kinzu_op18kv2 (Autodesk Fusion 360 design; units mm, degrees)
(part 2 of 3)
sketch "スケッチ73" plane through (0, 0, 0) normal (0, 0, 1) x axis (1, 0, 0)
  line L1 (-7.4, 45.9378) -> (-7.4, 47.6699)
  line L2 (7.4, 45.9378) -> (14.6149, 45.9378)
  line L3 (7.4, 47.6699) -> (7.4, 45.9378)
  line L4 (-7.4, 47.6699) -> (-15.2119, 47.6699)
  line L5 (-15.2119, 47.6699) -> (-7.4, 47.6699)
  line L6 (6.1, 41.5) -> (6.1, 45)
  line L7 (2.5, 42.5) -> (2.5, 41.5)
  line L8 (4.9, 42.5) -> (2.5, 42.5)
  line L9 (4.9, 45) -> (4.9, 42.5)
  line L10 (-2.5, 45) -> (-2.5, 46)
  line L11 (-4.9, 42.5) -> (-4.9, 45)
  line L12 (-2.5, 42.5) -> (-4.9, 42.5)
  line L13 (-2.5, 41.5) -> (-2.5, 42.5)
  line L14 (-6.1, 41.5) -> (-2.5, 41.5)
  line L15 (-6.1, 45) -> (-6.1, 41.5)
  line L16 (-50, 41.5) -> (50, 41.5)
  line L17 (-7.4, 41.5) -> (-7.4, 45)
  line L18 (-0.0015, 75) -> (-0.0015, 100)
  line L19 (50, -70) -> (-50, -70)
  line L20 (50, 70) -> (50, -70)
  line L21 (-50, 70) -> (50, 70)
  line L22 (-50, -70) -> (-50, 70)
  line L23 (50, 70) -> (-50, -70)
  line L24 (-50, 70) -> (50, -70)
  line L25 (-7.4, 70) -> (-7.4, 47.6699)
  line L26 (7.4, 41.5) -> (7.4, 45)
  line L27 (7.4, 70) -> (7.4, 47.6699)
  line L28 (2.5, 41.5) -> (6.1, 41.5)
  line L29 (7.4, 46) -> (2.5, 46)
  line L30 (6.1, 45) -> (7.4, 45)
  line L31 (2.5, 45) -> (4.9, 45)
  line L32 (2.5, 46) -> (2.5, 45)
  line L33 (-2.5, 46) -> (-7.4, 46)
  line L34 (-4.9, 45) -> (-2.5, 45)
  line L35 (-7.4, 45) -> (-6.1, 45)
  line L36 (8.6, 45.9378) -> (7.4, 45.9378)
  line L37 (8.6, 45) -> (8.6, 45.9378)
  line L38 (7.4, 45) -> (8.6, 45)
  line L39 (7.4, 45.9378) -> (7.4, 45)
  line L40 (-7.4, 45.9378) -> (-8.6, 45.9378)
  line L41 (-7.4, 45) -> (-7.4, 45.9378)
  line L42 (-8.6, 45) -> (-7.4, 45)
  line L43 (-8.6, 45.9378) -> (-8.6, 45)
  line L44 (-50, 47.6699) -> (-15.2119, 47.6699)
  line L45 (50, 47.6699) -> (15.2119, 47.6699)
  line L46 (-45, -5) -> (-45, 50)
  line L47 (45, -5) -> (45, 50)
  curve K1 (19.2629, 45.9378) -> (28.3953, -26.5255)
  curve K2 (15.2119, 47.6699) -> (19.2629, 45.9378)
  line L48 (7.4, 47.6699) -> (15.2119, 47.6699)
  line L49 (7.4, 45.9378) -> (7.4, 47.6699)
  line L50 (14.6149, 45.9378) -> (7.4, 45.9378)
  curve K3 (26.4543, -26.6056) -> (14.6149, 45.9378)
  curve K4 (-26.4543, -26.6056) -> (26.4543, -26.6056)
  curve K5 (-14.6149, 45.9378) -> (-26.4543, -26.6056)
  line L51 (-7.4, 45.9378) -> (-14.6149, 45.9378)
  line L52 (-7.4, 47.6699) -> (-7.4, 45.9378)
  line L53 (-15.2119, 47.6699) -> (-7.4, 47.6699)
  curve K6 (-19.2629, 45.9378) -> (-15.2119, 47.6699)
  curve K7 (-28.3953, -26.5255) -> (-19.2629, 45.9378)
  curve K8 (28.3953, -26.5255) -> (-28.3953, -26.5255)
  curve K9 (20.4801, -27.687) -> (-20.4801, -27.687)
  curve K10 (-24.4377, -27.1062) -> (-17.3148, 42.4442)
  curve K11 (17.3148, 42.4442) -> (24.4377, -27.1062)
  line L54 (14.7506, 70) -> (14.7506, 41.5)
  line L55 (-14.7512, 70) -> (-14.7512, 41.5)
  line L56 (-50, 4.113) -> (-21.6092, -24.2778)
  line L57 (-7, -23) -> (-20.387, -23)
  line L58 (50, 4.113) -> (21.6092, -24.2778)
  line L59 (45, -24) -> (20.887, -24)
  line L60 (48.6618, 5.9319) -> (8.6559, 45.9378)
  line L61 (-53.85, 0.7444) -> (-8.6565, 45.9378)
  line L62 (-10.164, 45) -> (-8.6, 45)
  line L63 (10.5, 45) -> (8.6, 45)
  line L64 (15.2119, 47.6699) -> (7.4, 47.6699)
  circle C1 centre (-24.4377, -27.1062) radius 4
  circle C2 centre (24.4377, -27.1062) radius 4
  circle C3 centre (-18.7512, 41.5) radius 4
  circle C4 centre (18.7506, 41.5) radius 4
  point P8 (-7.4, 47.6699)
  point P9 (-7.4, 47.6699)
  point P2 (-15.2119, 47.6699)
  point P10 (-15.2119, 47.6699)
  point P25 (-7.4, 41.5)
  point P32 (0, 0)
  point P1 (0, 0)
  point P3 (-7.4, 47.6699)
  point P33 (-7.4, 47.6699)
  point P34 (-7.4, 70)
  point P36 (7.4, 41.5)
  point P7 (7.4, 47.6699)
  point P37 (7.4, 47.6699)
  point P38 (7.4, 70)
  point P59 (-50, 47.6699)
  point P61 (50, 47.6699)
  point P83 (-24.4377, -27.1062)
  point P86 (-24.4377, -27.1062)
  point P84 (24.4377, -27.1062)
  point P87 (24.4377, -27.1062)
  point P88 (-18.7512, 41.5)
  point P89 (18.7506, 41.5)
  point P90 (14.7506, 41.5)
  point P91 (14.7506, 70)
  point P92 (-14.7512, 41.5)
  point P93 (-14.7512, 70)
  point P96 (-21.6092, -24.2778)
  point P99 (21.6092, -24.2778)
  point P100 (50, 4.113)
  point P101 (-50, 4.113)
  point P104 (8.6559, 45.9378)
  point P58 (-8.6, 45)
  point P106 (-8.6, 45)
  point P53 (8.6, 45)
  point P108 (8.6, 45)
  coincident P8 P9
  coincident P2 P10
  horizontal L16
  collinear L14 L16
  coincident L16 P25
  perpendicular L16 L17
  vertical L18
  horizontal L19
  perpendicular L19 L20
  parallel L19 L21
  parallel L20 L22
  coincident L23 P32
  coincident L24 P32
  coincident P1 P32
  coincident P3 P33
  coincident L21 P34
  perpendicular L21 L25
  coincident L16 P36
  perpendicular L16 L26
  coincident P7 P37
  coincident L21 P38
  perpendicular L21 L27
  coincident L22 P59
  perpendicular L22 L44
  coincident L20 P61
  perpendicular L20 L45
  perpendicular L44 L46
  perpendicular L16 L47
  coincident P83 P86
  coincident P84 P87
  coincident K10 P88
  coincident L16 P88
  coincident K11 P89
  coincident L16 P89
  coincident C4 P90
  coincident L16 P90
  coincident L21 P91
  tangent C4 L54
  coincident L16 P92
  coincident C3 P92
  coincident L21 P93
  tangent C3 L55
  horizontal L57
  tangent C1 L56
  coincident C1 P96
  horizontal L59
  tangent C2 L58
  coincident C2 P99
  coincident L20 P100
  coincident L22 P101
  tangent C4 L60
  tangent C3 L61
  coincident L2 P104
  coincident P58 P106
  perpendicular L43 L62
  coincident P53 P108
  perpendicular L37 L63
  dimension "d1064" = -8
  dimension "d1065" = -4
  dimension "d1069" diameter C1 = 8
  dimension "d1070" diameter C2 = 8
  dimension "d1071" diameter C3 = 8
  dimension "d1072" diameter C4 = 8
  dimension "d1073" angle L56 L57 = 135
  dimension "d1074" angle L58 L59 = 45
  dimension "d1157" angle L20 L60 = 45
  dimension "d1158" angle L22 L61 = 45
extrude "押し出し167" new body sketch "スケッチ73" profile of L1 L2 L3 L4 L5 L16 L19 L20 L22 L36 L37 L38 L39 L40 L41 L42 L43 L44 L45 L46 L47 K1 K2 L48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 along normal blind 2 bodies "feet"
combine "結合48"
sketch "スケッチ61" plane through (0, 0, 0) normal (0, 1, 0) x axis (1, 0, 0)
  line L1 (-50, 0) -> (50, 0)
  line L2 (0, -50) -> (0, 0)
  line L3 (-53.1, -8.7) -> (46.9, -8.7)
  curve K1 (-23.0212, -6.7064) -> (-3.1, -8.7)
  curve K2 (-26.0212, -6.7064) -> (-20.0212, -6.7064)
  curve K3 (-5.6533, -8.7) -> (-0.5467, -8.7)
  line L4 (-50, -6.7064) -> (-23.0212, -6.7064)
  line L5 (-40, -20) -> (-40, 5)
  line L6 (40, -20) -> (40, 5)
  line L7 (-3.1, -8.7) -> (0, -8.7)
  line L8 (-3.1, -10.2) -> (0, -10.2)
  curve K4 (-23.0212, -8.2064) -> (-3.1, -10.2)
  line L9 (-50, -8.2064) -> (-23.0212, -8.2064)
  line L10 (50, -8.2064) -> (23.0212, -8.2064)
  line L11 (50, -6.7064) -> (23.0212, -6.7064)
  curve K5 (23.0212, -6.7064) -> (3.1, -8.7)
  curve K6 (5.6533, -8.7) -> (0.5467, -8.7)
  curve K7 (26.0212, -6.7064) -> (20.0212, -6.7064)
  curve K8 (23.0212, -8.2064) -> (3.1, -10.2)
  line L12 (3.1, -8.7) -> (0, -8.7)
  line L13 (3.1, -10.2) -> (0, -10.2)
  line L14 (-3.1, -6.7) -> (0, -6.7)
  curve K9 (-23.0212, -4.7064) -> (-3.1, -6.7)
  line L15 (-50, -4.7064) -> (-23.0212, -4.7064)
  point P1 (0, 0)
  point P4 (0, 0)
  point P8 (-3.1, -8.7)
  point P20 (-23.0212, -6.7064)
  point P12 (-0.5467, -8.7)
  point P15 (-40, 5)
  point P17 (40, 5)
  point P16 (-40, -20)
  point P18 (40, -20)
  point P19 (0, -8.7)
  point P29 (3.1, -8.7)
  point P9 (-12, -7.8)
  point P30 (12, -7.8)
  point P10 (-20.0212, -6.7064)
  point P33 (20.0212, -6.7064)
  point P11 (-26.0212, -6.7064)
  point P34 (26.0212, -6.7064)
  point P31 (0.5467, -8.7)
  point P13 (-5.6533, -8.7)
  point P32 (5.6533, -8.7)
  point P14 (-50, -6.7064)
  point P28 (50, -6.7064)
  point P36 (0, -8.7)
  point P27 (23.0212, -6.7064)
  point P21 (0, -10.2)
  point P37 (0, -10.2)
  point P22 (-3.1, -10.2)
  point P35 (3.1, -10.2)
  point P23 (-23.0212, -8.2064)
  point P25 (23.0212, -8.2064)
  point P24 (-50, -8.2064)
  point P26 (50, -8.2064)
  horizontal L1
  coincident P1 P4
  perpendicular L1 L2
  midpoint L3 P8
  midpoint K2 P20
  midpoint P8 K3
  coincident L3 P12
  perpendicular L2 L4
  perpendicular L4 L5
  symmetric L2 P15 P17
  symmetric L2 P16 P18
  coincident P8 K3
  coincident L2 P19
  coincident L3 P19
  symmetric L2 P8 P29
  symmetric L2 P9 P30
  symmetric L2 P10 P33
  symmetric L2 P11 P34
  symmetric L2 P12 P31
  symmetric L2 P13 P32
  symmetric L2 P14 P28
  symmetric L2 P19 P36
  symmetric L2 P20 P27
  symmetric L2 P21 P37
  symmetric L2 P22 P35
  symmetric L2 P23 P25
  symmetric L2 K4 K8
  symmetric L2 P24 P26
  dimension "d719" = -8.7
  dimension "d959" distance P8 P19 = 3.1
  dimension "d963" = -1.5
  dimension "d1009" = 2
extrude "押し出し162" cut sketch "スケッチ61" profile of L2 L3 K1 L4 L5 L6 L7 L8 K4 L9 L10 L11 K5 K8 L12 L13 blind -10.5 from offset 55
sketch "スケッチ62" plane through (0, 0, 0) normal (1, 0, 0) x axis (0, 1, 0)
  curve K1 (-5, 23) -> (44.5, 8.2064)
  curve K2 (-10.1, 23) -> (0.1, 23)
  line L1 (-3.7887, 7.1804) -> (-3.7887, 25.1804)
  curve K3 (43, 8.2064) -> (46, 8.2064)
  curve K4 (-5, 21.5) -> (44.5, 6.7064)
  line L2 (44.5, 6.7064) -> (44.5, 8.2064)
  line L3 (49.5, 8.2064) -> (44.5, 8.2064)
  line L4 (49.5, 6.7064) -> (44.5, 6.7064)
  line L5 (-5, 45) -> (-5, 22.25)
  line L6 (-5, 0) -> (-5, 22.25)
  line L7 (48, 0) -> (-11, 0)
  line L8 (48, 35) -> (48, 0)
  line L9 (-11, 35) -> (48, 35)
  line L10 (-11, 0) -> (-11, 35)
  circle C1 centre (-5, 22.25) radius 0.75
  point P5 (-5, 23)
  point P2 (44.5, 8.2064)
  point P13 (-5, 21.5)
  point P18 (-5, 22.25)
  point P19 (-5, 22.25)
  point P21 (-5, 22.25)
  midpoint P5 K2
  vertical L1
  midpoint P2 K3
  perpendicular L2 L3
  coincident P13 C1
  coincident P5 C1
  coincident P18 P19
  vertical L5
  coincident P18 P21
  parallel L5 L6
  horizontal L7
  vertical L8
  horizontal L9
  vertical L10
  dimension "d724" = 1.5
  dimension "d917" = 1.5
sketch "スケッチ116" plane through (0, 0, 0) normal (1, 0, 0) x axis (0, 1, 0)
  curve K1 (-5, 23) -> (44.5, 8.2064)
  curve K2 (-5, 21.5) -> (44.5, 6.7064)
  line L1 (44.5, 6.7064) -> (44.5, 8.2064)
  arc A1 centre (-5, 22.25) radius 0.75 clockwise from (-5, 21.5) to (-5, 23)
  point P5 (-5, 21.5)
  point P8 (-5, 21.5)
  point P3 (-5, 23)
  point P7 (-5, 23)
  point P2 (44.5, 8.2064)
  point P9 (44.5, 8.2064)
  point P4 (44.5, 6.7064)
  point P10 (44.5, 6.7064)
  coincident P5 P8
  coincident P3 P7
  coincident P2 P9
  coincident P4 P10
copy_paste_bodies "ボディのコピーと貼り付け25"
move "移動27"
split "分割34" bodies "main (1)", "main (2)"
sketch "スケッチ114" plane through (0, 0, 0) normal (0, 0, 1) x axis (1, 0, 0)
  line L1 (0, -11) -> (0, 48)
  line L2 (-55, -5) -> (-10, -5)
  line L3 (-30, 0) -> (-30, -5)
  line L4 (-25, -5) -> (-35, 5)
  line L5 (-25.7071, -5.7071) -> (-35.7071, 4.2929)
  line L6 (-24.2929, -4.2929) -> (-34.2929, 5.7071)
  line L7 (25, -5) -> (35, 5)
  line L8 (25.7071, -5.7071) -> (35.7071, 4.2929)
  line L9 (30, 0) -> (30, -5)
  line L10 (24.2929, -4.2929) -> (34.2929, 5.7071)
  circle C1 centre (-35, 5) radius 1
  circle C2 centre (-25, -5) radius 1
  circle C3 centre (25, -5) radius 1
  circle C4 centre (35, 5) radius 1
  point P6 (-30, -5)
  point P9 (-25, -5)
  point P8 (-35, 5)
  point P10 (-35, 5)
  point P11 (-25, -5)
  point P23 (30, -5)
  point P7 (-30, 0)
  point P22 (30, 0)
  point P24 (35, 5)
  point P25 (25, -5)
  point P12 (-35.7071, 4.2929)
  point P21 (35.7071, 4.2929)
  point P13 (-25.7071, -5.7071)
  point P16 (25.7071, -5.7071)
  point P14 (-34.2929, 5.7071)
  point P19 (34.2929, 5.7071)
  point P15 (-24.2929, -4.2929)
  point P18 (24.2929, -4.2929)
  perpendicular L1 L2
  coincident L2 P6
  perpendicular L2 L3
  coincident L2 P9
  coincident P8 P10
  coincident P9 P11
  symmetric L1 P6 P23
  symmetric L1 P7 P22
  symmetric L1 P8 P24
  symmetric L1 P9 P25
  symmetric L1 C1 C4
  symmetric L1 C2 C3
  symmetric L1 P12 P21
  symmetric L1 P13 P16
  symmetric L1 P14 P19
  symmetric L1 P15 P18
  dimension "d1636" diameter C1 = 2
  dimension "d1637" diameter C2 = 2
  dimension "d1638" = 1
  dimension "d1639" = -1
extrude "押し出し265" new body sketch "スケッチ114" profile of L2 L3 L4 C1 C2 L5 L6 L7 C3 L8 C4 L9 L10 along normal blind 50
sketch "スケッチ115" plane through (0, 0, 0) normal (1, 0, 0) x axis (0, 1, 0)
  curve K1 (-5, 23) -> (44.5, 8.2064)
  line L1 (-15, 23) -> (-5, 23)
  point P3 (-5, 23)
  point P4 (-5, 23)
  coincident P3 P4
split "分割39" bodies "main (1) (1)", "main (1) (2)", "main (2) (1)", "main (2) (2)"
split "分割40" bodies "main (1) (3)", "main (1) (4)", "main (2) (2) (1)", "main (2) (2) (2)"
remove_body "RemoveBody36"
remove_body "RemoveBody37"
remove_body "RemoveBody38"
remove_body "RemoveBody39"
remove_body "RemoveBody40"
combine "結合75" bodies "main (1)", "main (1) (2)"
combine "結合76" bodies "main (1)", "main (1) (3)"
fillet "フィレット16" radius 3 5.5
combine "結合77"
sketch "スケッチ59" plane through (0, 0, 0) normal (0, 0, 1) x axis (1, 0, 0)
  line L1 (0, 125) -> (0, -125)
  line L2 (15.45, 1.7) -> (15.45, -7.3)
  line L3 (50, 0) -> (-50, 0)
  line L4 (50, -5) -> (-50, -5)
  line L5 (50, 125) -> (-50, 125)
  line L6 (50, -125) -> (-50, -125)
  line L7 (-4.075, 28.05) -> (-4.075, 32.35)
  line L8 (4.075, 32.35) -> (4.075, 28.05)
  line L9 (4.075, 30.2) -> (-4.075, 30.2)
  line L10 (4.075, 125) -> (4.075, -125)
  line L11 (-4.075, 125) -> (-4.075, -125)
  line L12 (6, 125) -> (6, -125)
  line L13 (-6, 125) -> (-6, -125)
  line L14 (0.5, 125) -> (0.5, -125)
  line L15 (-0.5, 125) -> (-0.5, -125)
  line L16 (50, 40) -> (-50, 40)
  line L17 (50, 26.5) -> (-50, 26.5)
  line L18 (3.9, 125) -> (3.9, -125)
  line L19 (-3.9, 125) -> (-3.9, -125)
  curve K1 (3.9, 40) -> (-3.9, 40)
  curve K2 (0, 42) -> (0, 38)
  curve K3 (3.9, 26.5) -> (-3.9, 26.5)
  curve K4 (0, 28.5) -> (0, 24.5)
  line L20 (-50, -125) -> (-50, 125)
  line L21 (50, 125) -> (50, -125)
  circle C1 centre (0, -5) radius 0.5
  closed curve K5 centre (0, 40)
  closed curve K6 centre (0, 26.5)
  point P18 (-4.075, 30.2)
  point P19 (4.075, 30.2)
  point P32 (0, -5)
  point P42 (-3.9, 40)
  point P43 (3.9, 40)
  point P44 (0, 38)
  point P45 (0, 42)
  point P47 (-3.9, 26.5)
  point P48 (3.9, 26.5)
  point P49 (0, 24.5)
  point P50 (0, 28.5)
  vertical L1
  perpendicular L2 L3
  perpendicular L1 L5
  perpendicular L1 L6
  midpoint L7 P18
  midpoint L8 P19
  midpoint L4 P32
  tangent L14 C1
  coincident K5 P42
  coincident K5 P43
  coincident K5 P44
  coincident K5 P45
  perpendicular L10 K1
  collinear L1 K2
  collinear L16 K1
  tangent L18 K5
  coincident K6 P47
  coincident K6 P48
  coincident K6 P49
  coincident K6 P50
  perpendicular L12 K3
  collinear L1 K4
  collinear L17 K3
  tangent L18 K6
  perpendicular L6 L20
  perpendicular L5 L21
  dimension "d920" = 5
  dimension "d921" = 4.075
  dimension "d922" = -4.075 (= "-d921")
  dimension "d923" = 6
  dimension "d924" = -6 (= "-d923")
  dimension "d928" = 0.5
  dimension "d929" = -0.5 (= "-d928")
  dimension "d933" = -40
  dimension "d934" = -26.5
  dimension "d935" = 3.9
  dimension "d936" = -3.9 (= "-d935")
  dimension "d939" = 4
  dimension "d940" = 4
extrude "押し出し166" cut sketch "スケッチ59" profile of L1 L3 L4 L5 L9 L14 L15 C1 L16 L17 L18 L19 K5 K6 blind 30 from offset 10
sketch "スケッチ77" plane through (0, 0, 7.4) normal (0, 0, 1) x axis (-1, 0, 0)
  line L1 (-7.6, -34.2) -> (-7.6, -35.6)
  line L2 (-6.8, -34.2) -> (-7.6, -34.2)
  line L3 (-6.8, -24.2) -> (-6.8, -34.2)
  line L4 (5.3, -22.2) -> (-4.8, -22.2)
  line L5 (7.6, -23.1) -> (6.6748, -23.1)
  line L6 (7.6, -24.9) -> (7.6, -23.1)
  line L7 (6.8, -24.9) -> (7.6, -24.9)
  line L8 (6.8, -34.2) -> (6.8, -24.9)
  line L9 (7.6, -34.2) -> (6.8, -34.2)
  line L10 (7.6, -36) -> (7.6, -34.2)
  line L11 (6.7596, -36) -> (7.6, -36)
  line L12 (-5.6, -37.6) -> (4.8, -37.6)
  line L13 (13.8, 9.7) -> (13.8, -14.4202)
  line L14 (10.1, 9.7) -> (13.8, 9.7)
  line L15 (10.1, 12.8) -> (10.1, 9.7)
  line L16 (2.3, 12.8) -> (10.1, 12.8)
  line L17 (2.3, 33.6) -> (2.3, 12.8)
  line L18 (-2.3, 33.6) -> (2.3, 33.6)
  line L19 (-2.3, 28.4) -> (-2.3, 33.6)
  line L20 (-7.3, 28.4) -> (-2.3, 28.4)
  line L21 (-7.3, 12.8) -> (-7.3, 28.4)
  line L22 (-9.3, 12.8) -> (-7.3, 12.8)
  line L23 (-9.3, 7.7) -> (-9.3, 12.8)
  line L24 (-14, 7.7) -> (-9.3, 7.7)
  line L25 (-14, -20.0176) -> (-14, 7.7)
  line L26 (-10.6, -39.3) -> (-14, -20.0176)
  line L27 (7.3, -39.3) -> (-10.6, -39.3)
  line L28 (10.1, -36.5) -> (7.3, -39.3)
  line L29 (13.8, -36.5) -> (10.1, -36.5)
  line L30 (13.8, -16.3798) -> (13.8, -36.5)
  line L31 (-4.3, -8.82) -> (4.3, -8.82)
  line L32 (-4.3, 8.44) -> (-4.3, -8.82)
  line L33 (4.3, 8.44) -> (-4.3, 8.44)
  line L34 (4.3, -8.82) -> (4.3, 8.44)
  line L35 (-9.8787, -13.9858) -> (-14.1213, -16.8142)
  line L36 (-9.8787, -13.9858) -> (-10.5858, -13.2787)
  line L37 (-14.1213, -16.8142) -> (-13.4142, -17.5213)
  line L38 (-10.5858, -13.2787) -> (-14.1213, -16.8142)
  line L39 (-13.4142, -17.5213) -> (-10.5858, -13.2787)
  line L40 (-13.4142, -17.5213) -> (-9.8787, -13.9858)
  line L41 (-9.8787, -16.8142) -> (-14.1213, -13.9858)
  line L42 (-10.5858, -17.5213) -> (-9.8787, -16.8142)
  line L43 (-13.4142, -13.2787) -> (-14.1213, -13.9858)
  line L44 (-14.1213, -13.9858) -> (-10.5858, -17.5213)
  line L45 (-9.8787, -16.8142) -> (-13.4142, -13.2787)
  line L46 (-13.4142, -13.2787) -> (-10.5858, -17.5213)
  line L47 (50, -75) -> (-50, -75)
  line L48 (50, 75) -> (50, -75)
  line L49 (-50, 75) -> (50, 75)
  line L50 (-50, -75) -> (-50, 75)
  line L51 (0.8, 31.8) -> (0, 31)
  line L52 (0, 32.6) -> (0.8, 31.8)
  line L53 (-0.8, 31.8) -> (0, 32.6)
  line L54 (0, 31) -> (-0.8, 31.8)
  line L55 (-65.8478, -6.2173) -> (65.8478, 69.8173)
  line L56 (-66.8478, -4.4852) -> (64.8478, 71.5493)
  line L57 (-64.8478, -7.9493) -> (66.8478, 68.0852)
  line L58 (-0.5, 33.8) -> (0.5, 33.8)
  line L59 (-0.5, 29.8) -> (-0.5, 33.8)
  line L60 (0.5, 29.8) -> (-0.5, 29.8)
  line L61 (0.5, 33.8) -> (0.5, 29.8)
  line L62 (-0.5, 29.8) -> (0.5, 33.8)
  line L63 (0.5, 29.8) -> (-0.5, 33.8)
  line L64 (0, 75) -> (0, -75)
  line L65 (-69.0865, -27.8871) -> (69.0865, 51.8871)
  line L66 (-67.0865, -31.3512) -> (71.0865, 48.423)
  line L67 (0, 12) -> (0, 0)
  line L68 (-12.8, -15.4) -> (-12, -14.6)
  line L69 (-12, -16.2) -> (-12.8, -15.4)
  line L70 (-11.2, -15.4) -> (-12, -16.2)
  line L71 (-12, -14.6) -> (-11.2, -15.4)
  line L72 (10.6787, -16.8142) -> (14.2142, -13.2787)
  line L73 (11.3858, -17.5213) -> (10.6787, -16.8142)
  line L74 (14.9213, -13.9858) -> (11.3858, -17.5213)
  line L75 (14.2142, -13.2787) -> (14.9213, -13.9858)
  line L76 (11.3858, -17.5213) -> (14.2142, -13.2787)
  line L77 (14.9213, -13.9858) -> (10.6787, -16.8142)
  line L78 (11.3858, -13.2787) -> (14.9213, -16.8142)
  line L79 (14.9213, -16.8142) -> (10.6787, -13.9858)
  line L80 (10.6787, -13.9858) -> (11.3858, -13.2787)
  line L81 (11.3858, -13.2787) -> (14.2142, -17.5213)
  line L82 (14.2142, -17.5213) -> (10.6787, -13.9858)
  line L83 (14.9213, -16.8142) -> (14.2142, -17.5213)
  line L84 (12, -15.4) -> (12.8, -14.6)
  line L85 (12.8, -16.2) -> (12, -15.4)
  line L86 (13.6, -15.4) -> (12.8, -16.2)
  line L87 (12.8, -14.6) -> (13.6, -15.4)
  arc A1 centre (-4.8, -24.2) radius 2 clockwise from (-6.8, -24.2) to (-4.8, -22.2)
  arc A2 centre (5.3, -23.7) radius 1.5 clockwise from (5.3, -22.2) to (6.6748, -23.1)
  arc A3 centre (4.8, -35.6) radius 2 clockwise from (6.7596, -36) to (4.8, -37.6)
  arc A4 centre (-5.6, -35.6) radius 2 clockwise from (-5.6, -37.6) to (-7.6, -35.6)
  circle C1 centre (0, 14.4) radius 1.4
  circle C2 centre (-12, -15.4) radius 1.4
  circle C3 centre (12.8, -15.4) radius 1.4
  circle C4 centre (-12, -15.4) radius 1.4
  circle C5 centre (0, 14.4) radius 1.4
  circle C6 centre (0, 14.4) radius 1.4
  circle C7 centre (0, 14.4) radius 0.7
  circle C8 centre (0, 14.4) radius 2
  circle C9 centre (0, 31.8) radius 1.4
  circle C10 centre (0, 31.8) radius 1.4
  circle C11 centre (0, 31.8) radius 2
  circle C12 centre (0, 9.6906) radius 2
  point P50 (-12, -15.4)
  point P57 (-12, -15.4)
  point P48 (-12, -15.4)
  point P61 (0, 14.4)
  point P62 (0, 14.4)
  point P59 (0, 14.4)
  point P63 (0, 14.4)
  point P70 (0, 31.8)
  point P75 (0, 31.8)
  point P69 (0, 31.8)
  point P87 (0, 31.8)
  point P88 (0, -75)
  point P89 (0, 75)
  point P1 (0, 0)
  point P94 (0, 0)
  point P95 (0, 12)
  point P100 (-12, -15.4)
  point P105 (12.8, -15.4)
  point P109 (12.8, -15.4)
  point P47 (12.8, -15.4)
  point P115 (12.8, -15.4)
  point P116 (0, 9.6906)
  point P49 (-9.8787, -13.9858)
  point P51 (-13.4142, -17.5213)
  point P53 (-10.5858, -13.2787)
  point P54 (-13.4142, -13.2787)
  point P55 (-9.8787, -16.8142)
  point P58 (-14.1213, -13.9858)
  point P71 (0, 31)
  point P85 (-0.5, 29.8)
  point P86 (0.5, 29.8)
  point P84 (-0.5, 33.8)
  point P96 (-12, -14.6)
  point P103 (11.3858, -17.5213)
  point P104 (14.9213, -13.9858)
  point P102 (10.6787, -16.8142)
  point P108 (11.3858, -13.2787)
  point P110 (14.9213, -16.8142)
  point P107 (14.2142, -17.5213)
  point P111 (12.8, -14.6)
  concentric C2 C4
  perpendicular L36 L38
  parallel L38 L40
  parallel L36 L37
  coincident P50 L35
  coincident P50 L39
  perpendicular L43 L44
  parallel L44 L45
  parallel L42 L43
  coincident P57 L46
  coincident P57 L41
  coincident P48 P50
  coincident P50 P57
  concentric C1 C5
  concentric C5 C6
  concentric C5 C7
  coincident P61 P62
  coincident P59 P63
  horizontal L47
  vertical L48
  horizontal L49
  vertical L50
  concentric C7 C8
  concentric C9 C10
  coincident P70 P75
  concentric C9 C11
  midpoint P69 L55
  horizontal L58
  perpendicular L58 L59
  parallel L58 L60
  parallel L59 L61
  coincident L62 P87
  coincident L63 P87
  coincident P75 P87
  midpoint L47 P88
  midpoint L49 P89
  coincident P1 P94
  perpendicular L33 L67
  midpoint L65 P95
  coincident P50 P100
  perpendicular L72 L73
  parallel L72 L74
  parallel L73 L75
  coincident L76 P105
  coincident L77 P105
  perpendicular L82 L83
  parallel L78 L82
  parallel L80 L83
  coincident P109 L79
  coincident P109 L81
  coincident P47 P109
  coincident P47 P105
  coincident P47 P115
  coincident L67 P116
  tangent L65 C12
  tangent L66 C12
  dimension "d1032" distance P49 P51 = 5
  dimension "d1033" distance P49 P53 = 1
  dimension "d1036" distance P54 P55 = 5
  dimension "d1037" distance P54 P58 = 1
  dimension "d1058" diameter C7 = 1.4
  dimension "d1164" diameter C8 = 4
  dimension "d1205" distance P71 P75 = 0.8
  dimension "d1206" diameter C11 = 4
  dimension "d1209" angle L49 L55 = 30
  dimension "d1210" = 2
  dimension "d1211" = -2 (= "-d1210")
  dimension "d1239" distance P85 P86 = 1
  dimension "d1240" distance P84 P85 = 4
  dimension "d1276" = -4
  dimension "d1277" angle L49 L65 = 30
  dimension "d1285" distance P94 P95 = 12
  dimension "d1348" distance P96 P100 = 0.8
  dimension "d1349" distance P103 P104 = 5
  dimension "d1350" distance P102 P103 = 1
  dimension "d1351" distance P108 P110 = 5
  dimension "d1352" distance P107 P110 = 1
  dimension "d1353" distance P111 P115 = 0.8
extrude "押し出し207" sketch "スケッチ77" profile of C9 C10 L51 L52 L53 L54 L55 blind 12 bodies "screw_b"
extrude "押し出し208" new body sketch "スケッチ77" profile of L17 L18 L19 L20 L21 L48 L50 C9 C10 L51 L52 L53 L54 C11 L55 L56 L57 along normal blind 20 and against normal blind 5
work_plane "作業平面" RotateAngle 90
sketch "スケッチ86" plane through (13.7698, -23.85, 0) normal (0.5, -0.866, 0) x axis (0.866, 0.5, 0)
  line L1 (41.835, 2.4) -> (-73.635, 2.4)
  line L2 (41.835, 27.4) -> (41.835, 2.4)
  line L3 (-73.635, 27.4) -> (41.835, 27.4)
  line L4 (-15.9, 27.4) -> (-15.9, 2.4)
  line L5 (-15.9, 17.4) -> (-15.9, 7.4)
  line L6 (82.1327, -14.4527) -> (-113.9327, 49.2527)
  line L7 (60.1345, 7.4) -> (-91.9345, 7.4)
  line L8 (83.0597, -11.5996) -> (-113.0056, 52.1059)
  line L9 (75, 50) -> (-100, 50)
  line L10 (75, -25) -> (75, 50)
  line L11 (-100, -25) -> (75, -25)
  line L12 (-100, 50) -> (-100, -25)
  line L13 (-73.635, 2.4) -> (-73.635, 27.4)
  point P6 (-15.9, 2.4)
  point P7 (-15.9, 27.4)
  point P8 (-15.9, 7.4)
  point P9 (-15.9, 7.4)
  point P10 (-15.9, 17.4)
  midpoint L1 P6
  midpoint L3 P7
  coincident P8 P9
  perpendicular L3 L5
  midpoint P10 L6
  horizontal L9
  vertical L10
  horizontal L11
  vertical L12
  dimension "d1217" distance P9 P10 = 10
  dimension "d1218" angle L6 L7 = 18
  dimension "d1219" = -3
extrude "押し出し209" cut sketch "スケッチ86" profile of L1 L2 L3 L4 L5 L6 L7 L8 L9 L10 L11 L12 distance 5
combine "結合59"
mirror "ミラー11" mirrorStitchTolerance 0.1
split "分割30"
shell "シェル25" innerThickness 1.03
combine "結合69"
extrude "押し出し211" new body sketch "スケッチ77" profile of L18 C9 C10 C11 L58 L59 L60 L61 L64 to an object
chamfer "面取り10" distance 0.2
combine "結合74"
sketch "スケッチ108" plane through (0, 0, 6.6) normal (0, 0, -1) x axis (1, 0, 0)
  line L1 (0.8, 31.8) -> (0, 32.6)
  line L2 (0, 31) -> (0.8, 31.8)
  line L3 (-0.8, 31.8) -> (0, 31)
  line L4 (0, 32.6) -> (-0.8, 31.8)
  circle C1 centre (0, 31.8) radius 1.4
  circle C2 centre (0, 31.8) radius 1.3
  dimension "d1559" = -0.1
extrude "押し出し257" cut sketch "スケッチ108" profile of C1 C2 to an object
extrude "押し出し214" new body sketch "スケッチ77" profile of L16 L17 L25 L32 L33 L48 L50 L64 L65 L66 L67 along normal blind 30 and against normal blind 7 bodies "rib_b"
sketch "スケッチ91" plane through (5.1962, -9, 0) normal (0.5, -0.866, 0) x axis (0.866, 0.5, 0)
  line L1 (51.735, 37.4) -> (51.735, 0.4)
  line L2 (-63.735, 37.4) -> (51.735, 37.4)
  line L3 (51.735, 0.4) -> (-63.735, 0.4)
  line L4 (54.0444, 37.4) -> (54.0444, 0.4)
  line L5 (51.735, 37.4) -> (54.0444, 37.4)
  line L6 (51.735, 0.4) -> (51.735, 37.4)
  line L7 (54.0444, 0.4) -> (51.735, 0.4)
  line L8 (39.6724, -1.5049) -> (-39.6724, 44.3049)
  line L9 (45.0445, -1.1424) -> (-38.1724, 46.903)
  line L10 (-63.735, 0.4) -> (-63.735, 37.4)
  line L11 (1.654, 7.4) -> (-0.078, 7.4)
  line L12 (0, 21.4) -> (0, 7.4)
  point P16 (0, 7.4)
  point P17 (0, 21.4)
  coincident L11 P16
  perpendicular L3 L12
  midpoint L8 P17
  dimension "d1279" = -3
  dimension "d1280" angle L2 L9 = 30
  dimension "d1286" distance P16 P17 = 14
extrude "押し出し216" cut sketch "スケッチ91" profile of L1 L2 L3 L4 L5 L6 L7 L8 L9 L10 against normal blind 19.125
mirror "ミラー13" mirrorStitchTolerance 0.1 bodies "rib_b (1)"
split "分割31" bodies "rib_b (2)", "rib_b (1) (1)"
shell "シェル26" innerThickness 1.03
combine "結合70" bodies "rib_b (1)", "rib_b (2)", "rib_b (1) (1)"
combine "結合62"
sketch "スケッチ75" plane through (0, 4.4063, 17.9537) normal (0, 0.342, 0.9397) x axis (-1, 0, 0)
  line L1 (15.6, -9.7904) -> (15.6, -4.0904)
  line L2 (16.15, -31.4904) -> (16.15, -11.7873)
  line L3 (22.85, -31.4904) -> (16.15, -31.4904)
  line L4 (22.85, -11.7873) -> (22.85, -31.4904)
  line L5 (23.4, -4.0904) -> (23.4, -9.7904)
  line L6 (15.6, -4.0904) -> (23.4, -4.0904)
  line L7 (16.5, -27.3904) -> (22.5, -27.3904)
  line L8 (16.5, -28.5904) -> (16.5, -27.3904)
  line L9 (22.5, -28.5904) -> (16.5, -28.5904)
  line L10 (22.5, -27.3904) -> (22.5, -28.5904)
  line L11 (16.5, -28.5904) -> (22.5, -27.3904)
  line L12 (22.5, -28.5904) -> (16.5, -27.3904)
  line L13 (22.5, -9.1904) -> (16.5, -9.1904)
  line L14 (22.5, -10.3904) -> (22.5, -9.1904)
  line L15 (16.5, -10.3904) -> (22.5, -10.3904)
  line L16 (16.5, -9.1904) -> (16.5, -10.3904)
  line L17 (22.5, -10.3904) -> (16.5, -9.1904)
  line L18 (16.5, -10.3904) -> (22.5, -9.1904)
  line L19 (20.1, -24.9904) -> (18.9, -24.9904)
  line L20 (20.1, -30.9904) -> (20.1, -24.9904)
  line L21 (18.9, -30.9904) -> (20.1, -30.9904)
  line L22 (18.9, -24.9904) -> (18.9, -30.9904)
  line L23 (20.1, -30.9904) -> (18.9, -24.9904)
  line L24 (18.9, -30.9904) -> (20.1, -24.9904)
  line L25 (20.1, -6.7904) -> (18.9, -6.7904)
  line L26 (20.1, -12.7904) -> (20.1, -6.7904)
  line L27 (18.9, -12.7904) -> (20.1, -12.7904)
  line L28 (18.9, -6.7904) -> (18.9, -12.7904)
  line L29 (20.1, -12.7904) -> (18.9, -6.7904)
  line L30 (18.9, -12.7904) -> (20.1, -6.7904)
  line L31 (22.85, -27.9904) -> (19.5, -27.9904)
  line L32 (23.5, -30.3154) -> (19.5, -30.3154)
  line L33 (23.5, -25.6654) -> (23.5, -30.3154)
  line L34 (19.5, -25.6654) -> (23.5, -25.6654)
  line L35 (19.5, -30.3154) -> (19.5, -25.6654)
  line L36 (32.6, -18.8904) -> (23.5, -27.9904)
  line L37 (28.8915, -27.9904) -> (23.5, -27.9904)
  line L38 (34.244, -20.5344) -> (25.144, -29.6344)
  line L39 (30.956, -17.2464) -> (21.856, -26.3464)
  line L40 (0.6665, -50.8239) -> (23.5, -27.9904)
  line L41 (2.3105, -52.4679) -> (25.144, -29.6344)
  line L42 (-0.9775, -49.1799) -> (21.856, -26.3464)
  line L43 (14.3, -12.1154) -> (19.5, -12.1154)
  line L44 (14.3, -7.4654) -> (14.3, -12.1154)
  line L45 (19.5, -7.4654) -> (14.3, -7.4654)
  line L46 (19.5, -12.1154) -> (19.5, -7.4654)
  line L47 (11.0055, -8.0093) -> (11.0034, -8.0111)
  line L48 (11.0755, -7.953) -> (11.0598, -7.9652)
  line L49 (-16.1077, -35.3055) -> (44.7077, 15.7247)
  line L50 (-40, -60) -> (40, -60)
  line L51 (-40, 70) -> (-40, -60)
  line L52 (40, 70) -> (-40, 70)
  line L53 (40, -60) -> (40, 70)
  line L54 (0, 70) -> (0, -60)
  line L55 (-17.4849, -33.426) -> (43.3306, 17.6043)
  line L56 (-14.4959, -36.9881) -> (46.3196, 14.0422)
  line L57 (40, -9.7904) -> (19.5, -9.7904)
  line L58 (-11.5069, -40.5502) -> (49.3085, 10.4801)
  line L59 (21.5341, -12.1154) -> (19.5, -12.1154)
  line L60 (21.5341, -7.4654) -> (21.5341, -12.1154)
  line L61 (19.5, -7.4654) -> (21.5341, -7.4654)
  line L62 (19.5, -12.1154) -> (19.5, -7.4654)
  line L63 (19.5, -31.9904) -> (19.5, -27.9904)
  line L64 (21.825, -31.9904) -> (21.825, -27.9904)
  line L65 (17.175, -31.9904) -> (17.175, -27.9904)
  line L66 (18.7, -27.9904) -> (19.5, -27.1904)
  line L67 (19.5, -28.7904) -> (18.7, -27.9904)
  line L68 (20.3, -27.9904) -> (19.5, -28.7904)
  line L69 (19.5, -27.1904) -> (20.3, -27.9904)
  line L70 (18.7, -9.7904) -> (19.5, -8.9904)
  line L71 (19.5, -10.5904) -> (18.7, -9.7904)
  line L72 (20.3, -9.7904) -> (19.5, -10.5904)
  line L73 (19.5, -8.9904) -> (20.3, -9.7904)
  line L74 (4.075, -119.4616) -> (4.075, 115.4616)
  line L75 (17.4849, -33.426) -> (-43.3306, 17.6043)
  line L76 (18.05, -20.2404) -> (20.95, -20.2404)
  line L77 (18.05, -21.4404) -> (18.05, -20.2404)
  line L78 (20.95, -21.4404) -> (18.05, -21.4404)
  line L79 (20.95, -20.2404) -> (20.95, -21.4404)
  line L80 (17.55, -19.7404) -> (21.45, -19.7404)
  line L81 (17.55, -21.9404) -> (17.55, -19.7404)
  line L82 (21.45, -21.9404) -> (17.55, -21.9404)
  line L83 (21.45, -19.7404) -> (21.45, -21.9404)
  circle C1 centre (19.5, -9.7904) radius 2.325
  circle C2 centre (19.5, -27.9904) radius 2.325
  arc A1 centre (19.5, -9.7904) radius 3.9 clockwise from (16.15, -11.7873) to (15.6, -9.7904)
  arc A2 centre (19.5, -9.7904) radius 3.9 clockwise from (23.4, -9.7904) to (22.85, -11.7873)
  circle C3 centre (23.5, -27.9904) radius 2.325
  circle C4 centre (32.6, -18.8904) radius 2.325
  circle C5 centre (0.6665, -50.8239) radius 2.325
  circle C6 centre (14.3, -9.7904) radius 2.325
  circle C7 centre (21.5341, -9.7904) radius 2.325
  circle C8 centre (19.5, -31.9904) radius 2.325
  point P16 (19.5, -27.9904)
  point P3 (19.5, -27.9904)
  point P21 (19.5, -9.7904)
  point P2 (19.5, -9.7904)
  point P26 (19.5, -27.9904)
  point P31 (19.5, -9.7904)
  point P32 (19.5, -27.9904)
  point P33 (22.85, -27.9904)
  point P34 (19.5, -30.3154)
  point P38 (23.5, -27.9904)
  point P35 (23.5, -30.3154)
  point P39 (23.5, -27.9904)
  point P40 (32.6, -18.8904)
  point P42 (32.6, -18.8904)
  point P43 (25.144, -29.6344)
  point P44 (21.856, -26.3464)
  point P45 (34.244, -20.5344)
  point P46 (30.956, -17.2464)
  point P49 (23.5, -27.9904)
  point P47 (0.6665, -50.8239)
  point P50 (0.6665, -50.8239)
  point P51 (2.3105, -52.4679)
  point P52 (-0.9775, -49.1799)
  point P66 (0, -60)
  point P67 (0, 70)
  point P72 (14.3, -9.7904)
  point P73 (19.5, -9.7904)
  point P74 (40, -9.7904)
  point P75 (21.5341, -9.7904)
  point P79 (21.5341, -7.4654)
  point P81 (19.5, -27.9904)
  point P82 (19.5, -31.9904)
  point P83 (19.5, -31.9904)
  point P84 (21.825, -27.9904)
  point P85 (21.825, -31.9904)
  point P86 (17.175, -27.9904)
  point P92 (19.5, -27.9904)
  point P88 (19.5, -27.1904)
  point P93 (19.5, -8.9904)
  point P68 (43.3306, 17.6043)
  point P100 (-43.3306, 17.6043)
  point P69 (-17.4849, -33.426)
  point P101 (17.4849, -33.426)
  point P14 (16.5, -28.5904)
  point P15 (22.5, -28.5904)
  point P13 (16.5, -27.3904)
  point P19 (22.5, -10.3904)
  point P20 (16.5, -10.3904)
  point P18 (22.5, -9.1904)
  point P24 (20.1, -30.9904)
  point P25 (18.9, -30.9904)
  point P23 (20.1, -24.9904)
  point P29 (20.1, -12.7904)
  point P30 (18.9, -12.7904)
  point P28 (20.1, -6.7904)
  point P48 (19.5, -12.1154)
  point P53 (14.3, -12.1154)
  point P97 (19.5, -9.7904)
  horizontal L7
  perpendicular L7 L8
  parallel L7 L9
  parallel L8 L10
  coincident L11 P16
  coincident L12 P16
  coincident P3 P16
  horizontal L13
  perpendicular L13 L14
  parallel L13 L15
  parallel L14 L16
  coincident L17 P21
  coincident L18 P21
  coincident P2 P21
  horizontal L19
  perpendicular L19 L20
  parallel L19 L21
  parallel L20 L22
  coincident L23 P26
  coincident L24 P26
  coincident P3 P26
  horizontal L25
  perpendicular L25 L26
  parallel L25 L27
  parallel L26 L28
  coincident L29 P31
  coincident L30 P31
  coincident P21 P31
  coincident P16 P32
  coincident L4 P33
  perpendicular L4 L31
  horizontal L32
  vertical L33
  horizontal L34
  vertical L35
  coincident C2 P34
  tangent C2 L34
  midpoint L33 P38
  coincident P35 C3
  horizontal L37
  coincident P38 P39
  coincident P40 P42
  tangent C3 L38
  tangent C4 L38
  tangent C3 L39
  tangent C4 L39
  coincident C3 P43
  coincident C3 P44
  coincident C4 P45
  coincident C4 P46
  coincident P38 P49
  coincident P47 P50
  coincident C5 P51
  tangent C5 L41
  coincident C5 P52
  tangent C5 L42
  horizontal L43
  vertical L44
  horizontal L45
  vertical L46
  tangent C1 L43
  midpoint P2 L46
  horizontal L50
  vertical L51
  horizontal L52
  vertical L53
  midpoint L50 P66
  midpoint L52 P67
  midpoint L44 P72
  midpoint L49 P72
  coincident P31 P73
  coincident L53 P74
  perpendicular L53 L57
  tangent L56 C7
  coincident L57 P75
  horizontal L59
  vertical L60
  horizontal L61
  vertical L62
  coincident C7 P79
  coincident P16 P81
  coincident L40 P82
  perpendicular L3 L63
  coincident P82 P83
  coincident C2 P84
  coincident L31 P84
  coincident C8 P85
  tangent C8 L64
  coincident C2 P86
  tangent C2 L65
  perpendicular L3 L65
  coincident P26 P92
  coincident L35 P88
  coincident L46 P93
  symmetric L54 P68 P100
  symmetric L54 P69 P101
  dimension "d973" distance P14 P15 = 6
  dimension "d974" distance P13 P14 = 1.2
  dimension "d975" distance P19 P20 = 6
  dimension "d976" distance P18 P19 = 1.2
  dimension "d977" distance P24 P25 = 1.2
  dimension "d978" distance P23 P24 = 6
  dimension "d979" distance P29 P30 = 1.2
  dimension "d980" distance P28 P29 = 6
  dimension "d995" distance P34 P35 = 4
  dimension "d996" angle L36 L37 = 45
  dimension "d997" diameter C4 = 4.65
  dimension "d1005" diameter C5 = 4.65
  dimension "d1050" angle L9 L40 = 45
  dimension "d1102" distance P48 P53 = 5.2
  dimension "d1289" angle L13 L49 = 40
  dimension "d1290" = 2.325
  dimension "d1291" = -2.325 (= "-d1290")
  dimension "d1294" diameter C6 = 4.65
  dimension "d1304" diameter C7 = 4.65
  dimension "d1305" = -4.65
  dimension "d1327" diameter C8 = 4.65
  dimension "d1335" distance P88 P92 = 0.8
  dimension "d1336" distance P93 P97 = 0.8
  dimension "d1366" = 0.5
extrude "押し出し169" sketch "スケッチ75" profile of C1 C2 L7 L9 L13 L15 L20 L22 L26 L28 L31 L35 C3 L42 L46 L56 L57 C7 L60 L62 L63 C8 L66 L67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 blind 5.8 (= "0.8 mm + 1 mm + 2 mm + 2 mm")
extrude "押し出し225" add sketch "スケッチ75" profile of C1 C2 L7 L9 L10 L13 L14 L15 L16 L20 L21 L22 L31 L32 L56 C6 L57 L63 L64 to an object
extrude "押し出し171" sketch "スケッチ75" profile of C2 L4 L7 L9 L10 L20 L22 L31 L32 L33 L34 L35 C3 L36 C4 L38 L39 L40 L42 L63 C8 L64 L66 L67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 blind 2 from offset 1
combine "結合65"
extrude "押し出し173" sketch "スケッチ75" profile of C2 L3 L7 L9 L20 L21 L22 L31 L32 L35 C3 C5 L40 L41 L42 L54 L63 C8 L64 L65 L66 L67 L68 L69 blind 2
extrude "押し出し185" cut sketch "スケッチ58" profile of A1 L1 L2 L3 L4 A2 L5 L6 L7 L8 C1 L9 L10 L11 L12 L13 L14 L15 L16 L17 L18 L19 L20 L22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 along normal blind 80.427
extrude "押し出し186" cut of existing geometry blind 4.161
extrude "押し出し220" new body sketch "スケッチ75" profile of C1 A2 L5 L13 L14 L15 L26 L28 L46 L53 L56 L57 C7 L58 L59 L60 L61 L62 L70 L71 L72 L73 blind 2 from offset 1
combine "結合63"
extrude "押し出し217" sketch "スケッチ75" profile of C1 L1 A1 L2 L13 L15 L16 L26 L28 L43 L44 L45 L46 L49 L55 L56 C6 L57 C7 L60 L62 L70 L71 L72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 blind 2
extrude "押し出し177" sketch "スケッチ77" profile of L13 L25 L30 C2 C3 C4 L37 L38 L40 L42 L43 L44 L45 L68 L69 L70 L71 L72 L73 L74 L75 L78 L82 L83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 blind 10.584
extrude "押し出し253" cut sketch "スケッチ77" profile of C2 C3 C4 L38 L40 L44 L45 L68 L69 L70 L71 L72 L74 L78 L82 L84 L85 L86 L87 along normal blind 0.4
chamfer "面取り9" distance 0.4
extrude "押し出し236" add sketch "スケッチ77" profile of C2 C3 C4 L38 L40 L44 L45 L68 L69 L70 L71 L72 L74 L78 L82 L84 L85 L86 L87 to an object from offset 1
sketch "スケッチ107" plane through (0, 0, 6.6) normal (0, 0, -1) x axis (1, 0, 0)
  line L1 (-13.6, -15.4) -> (-12.8, -16.2)
  line L2 (-12.8, -14.6) -> (-13.6, -15.4)
  line L3 (-12, -15.4) -> (-12.8, -14.6)
  line L4 (-12.8, -16.2) -> (-12, -15.4)
  line L5 (11.2, -15.4) -> (12, -16.2)
  line L6 (12, -14.6) -> (11.2, -15.4)
  line L7 (12.8, -15.4) -> (12, -14.6)
  line L8 (12, -16.2) -> (12.8, -15.4)
  circle C1 centre (-12.8, -15.4) radius 1.4
  circle C2 centre (12, -15.4) radius 1.4
  circle C3 centre (12, -15.4) radius 1.3
  circle C4 centre (-12.8, -15.4) radius 1.3
  dimension "d1551" = -0.1
  dimension "d1552" = -0.1
extrude "押し出し255" cut sketch "スケッチ107" profile of C1 C2 C3 C4 to an object
extrude "押し出し231" sketch "スケッチ75" profile of L76 L77 L78 L79 L80 L81 L82 L83 to an object
draft "勾配1" Angle1 30 Angle2 0
extrude "押し出し164" new body sketch "スケッチ59" profile of L3 L4 L5 L6 L7 L8 L10 L11 L12 L13 L16 L17 blind 30 from offset 7.4 bodies "whl_L", "whl_R"
sketch "スケッチ74" plane through (0, 0, 0) normal (1, 0, 0) x axis (0, 1, 0)
  curve K1 (-32.2138, 32.9056) -> (50.0524, 13.9615)
  curve K2 (-54.5051, 18.1466) -> (-32.2138, 32.9056)
  curve K3 (-65.5231, 5.6477) -> (-54.5051, 18.1466)
  line L1 (-70.0464, 0) -> (-65.5231, 5.6477)
  line L2 (-68.509, 0) -> (-70.0464, 0)
  line L3 (-64.5865, 4.8975) -> (-68.509, 0)
  curve K4 (-53.6799, 17.2754) -> (-64.5865, 4.8975)
  curve K5 (-31.7526, 31.7978) -> (-53.6799, 17.2754)
  curve K6 (49.3444, 12.9926) -> (-31.7526, 31.7978)
  curve K7 (50.1636, 2.8111) -> (49.3444, 12.9926)
  line L4 (49.4515, 0) -> (50.1636, 2.8111)
  line L5 (50.6894, 0) -> (49.4515, 0)
  line L6 (51.3269, 2.5164) -> (50.6894, 0)
  curve K8 (50.0524, 13.9615) -> (51.3269, 2.5164)
  line L7 (50.9608, 8.7) -> (50.2679, 7.5)
  line L8 (41.5, 8.7) -> (50.9608, 8.7)
  line L9 (41.5, 7.5) -> (41.5, 8.7)
  line L10 (50.2679, 7.5) -> (41.5, 7.5)
  line L11 (1.7, 12.4) -> (-7.3, 12.4)
  line L12 (0, 50) -> (0, 0)
  line L13 (125, 50) -> (125, 0)
  line L14 (-125, 0) -> (-125, 50)
  line L15 (125, 0) -> (-125, 0)
  line L16 (-125, 50) -> (125, 50)
  line L17 (29.125, 50) -> (29.125, 0)
  line L18 (31.275, 0) -> (31.275, 50)
  line L19 (28.4, 0) -> (28.4, 50)
  line L20 (32, 0) -> (32, 50)
  line L21 (-125, 7.5) -> (125, 7.5)
  line L22 (-125, 8.7) -> (125, 8.7)
  curve K9 (47.8695, 10.974) -> (-30.7916, 29.4899)
  curve K10 (49.2756, 9.8551) -> (47.8695, 10.974)
  curve K11 (47.7402, 3.425) -> (49.2756, 9.8551)
  line L23 (-125, 16.4) -> (125, 16.4)
  line L24 (-125, 14.4) -> (125, 14.4)
  line L25 (150, 0) -> (150, 50)
  line L26 (35.7831, 14.4169) -> (41.5, 8.7)
  line L27 (49.5849, 8.7) -> (41.5, 8.7)
  line L28 (33.2192, 21.9306) -> (46.4497, 8.7)
  line L29 (30.8501, 8.7) -> (46.4497, 8.7)
  line L30 (41.5, 8.7) -> (41.5, 7.5025)
  line L31 (45, 8.7) -> (41.5, 8.7)
  line L32 (45, 8.7) -> (45, 7.5025)
  line L33 (41.5, 7.5025) -> (45, 7.5025)
  line L34 (45, 10.1497) -> (45, 8.7)
  line L35 (-125, 22.4456) -> (125, 22.4456)
  circle C1 centre (30.2, 16.4) radius 1.075
  circle C2 centre (30.2, 16.4) radius 1.8
  circle C3 centre (30.2, 16.4) radius 2
  circle C4 centre (30.2, 16.4) radius 1.275
  point P1 (0, 0)
  point P22 (0, 0)
  point P30 (29.125, 0)
  point P31 (29.125, 50)
  point P32 (31.275, 50)
  point P33 (31.275, 0)
  point P34 (28.4, 50)
  point P35 (28.4, 0)
  point P36 (32, 50)
  point P37 (32, 0)
  point P29 (30.2, 16.4)
  point P18 (41.5, 8.7)
  point P52 (41.5, 8.7)
  point P55 (46.4497, 8.7)
  point P60 (45, 8.7)
  point P62 (45, 8.7)
  point P63 (45, 10.1497)
  coincident P1 P22
  perpendicular L11 L12
  vertical L13
  parallel L12 L14
  perpendicular L13 L15
  perpendicular L12 L16
  coincident L15 P30
  coincident L16 P31
  perpendicular L16 L17
  tangent C1 L17
  coincident L16 P32
  coincident L15 P33
  perpendicular L15 L18
  tangent C1 L18
  coincident L16 P34
  coincident L15 P35
  perpendicular L15 L19
  coincident L16 P36
  coincident L15 P37
  perpendicular L15 L20
  tangent C2 L19
  tangent C2 L20
  perpendicular L18 L21
  collinear L10 L21
  horizontal L22
  collinear L8 L22
  horizontal L23
  coincident P29 L23
  parallel L13 L25
  horizontal L27
  coincident P18 P52
  horizontal L29
  coincident L27 P55
  coincident P60 P62
  perpendicular L31 L34
  coincident L28 P63
  dimension "d1042" = 2.5
  dimension "d1043" = -2
  dimension "d1046" angle L26 L27 = 135
  dimension "d1047" angle L28 L29 = 45
  dimension "d1049" distance L26 L28 = 3.5
  dimension "d1613" = 0.2
  dimension "d1614" = 0.2
extrude "押し出し178" cut sketch "スケッチ74" profile of K1 K2 K3 L1 L2 L3 K4 K5 K6 K7 L4 L5 L6 K8 L7 L8 L9 L10 L12 L13 L14 L15 L16 C1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 distance -6
extrude "押し出し179" cut sketch "スケッチ74" profile of L15 C1 C2 L17 L18 L19 L20 L21 L22 L23 L24 C3 C4 along normal blind 11.004
sketch "スケッチ95" plane through (-6, 0, 0) normal (-1, 0, 0) x axis (0, -1, 0)
  line L1 (-29.125, 8.7) -> (-29.125, 17.0856)
  line L2 (-31.275, 17.0856) -> (-31.275, 14.4)
  line L3 (-24.7129, 15.8836) -> (-19.0088, 17.9597)
  line L4 (-24.0288, 14.0042) -> (-24.7129, 15.8836)
  line L5 (-19.0088, 17.9597) -> (-18.3248, 16.0804)
  line L6 (-18.3248, 16.0804) -> (-24.0288, 14.0042)
  line L7 (-29.125, 14.0042) -> (-24.0288, 14.0042)
  line L8 (-19.0088, 37.4) -> (-19.0088, 17.9597)
  line L9 (0, 31.9533) -> (0, 8.7)
  curve K1 (-28.0869, 22.4456) -> (0, 31.9533)
  line L10 (-45, 10.1497) -> (-37.9528, 17.197)
  line L11 (-45, 8.7) -> (-45, 10.1497)
  line L12 (-45, 7.5025) -> (-45, 8.7)
  line L13 (-41.5, 7.5025) -> (-45, 7.5025)
  line L14 (-41.5, 8.7) -> (-41.5, 7.5025)
  curve K2 (-28.4, 22.2909) -> (-28.0869, 22.4456)
  line L15 (-31.275, 14.4) -> (-35.8, 14.4)
  curve K3 (-29.125, 21.9297) -> (-28.4, 22.2909)
  curve K4 (-31.275, 20.8335) -> (-29.125, 21.9297)
  line L16 (-35.8, 14.4) -> (-41.5, 8.7)
  curve K5 (-32, 20.4556) -> (-31.275, 20.8335)
  line L17 (-37.8921, 28.862) -> (-19.0088, 17.9597)
  line L18 (0, 8.7) -> (-29.125, 8.7)
  curve K6 (-37.9528, 17.197) -> (-32, 20.4556)
  arc A1 centre (-30.2, 16.4) radius 1.275 clockwise from (-31.275, 17.0856) to (-29.125, 17.0856)
  point P9 (-24.0288, 14.0042)
  point P14 (-24.0288, 14.0042)
  point P15 (-29.125, 14.0042)
  point P6 (-19.0088, 17.9597)
  point P16 (-19.0088, 17.9597)
  coincident P9 P14
  coincident L1 P15
  perpendicular L1 L7
  coincident P6 P16
  dimension "d1339" angle L8 L17 = 60
extrude "押し出し226" cut sketch "スケッチ95" profile of L5 L6 L7 L8 L9 K1 L17 against normal blind 29.526
extrude "押し出し227" cut sketch "スケッチ75" profile of L1 L6 L51 L52 L53 L54 L55 L74 L75 along normal blind 19.393
sketch "スケッチ99" plane through (0, 7.3117, 20.0888) normal (0, -0.342, -0.9397) x axis (1, 0, 0)
  line L1 (-18.7, -7.7904) -> (-19.5, -6.9904)
  line L2 (-19.5, -8.5904) -> (-18.7, -7.7904)
  line L3 (-20.3, -7.7904) -> (-19.5, -8.5904)
  line L4 (-19.5, -6.9904) -> (-20.3, -7.7904)
  line L5 (-19.5, -5.4654) -> (-14.3, -5.4654)
  line L6 (-15.1462, -10.1154) -> (-19.5, -10.1154)
  line L7 (-4.075, -19.4053) -> (-15.1462, -10.1154)
  line L8 (-4.075, -13.3351) -> (-4.075, -19.4053)
  line L9 (-12.8055, -6.0093) -> (-4.075, -13.3351)
  line L10 (-6, -11.7198) -> (-4.075, -13.3351)
  line L11 (-6, -17.79) -> (-6, -11.7198)
  line L12 (-4.075, -17.79) -> (-6, -17.79)
  line L13 (-4.075, -13.3351) -> (-4.075, -17.79)
  line L14 (-7.1392, -10.764) -> (-4.075, -13.3351)
  line L15 (14.0786, 14.5224) -> (17.1428, 11.9513)
  line L16 (-4.075, -13.3351) -> (17.1428, 11.9513)
  line L17 (14.0786, 14.5224) -> (-7.1392, -10.764)
  arc A1 centre (-19.5, -7.7904) radius 2.325 clockwise from (-19.5, -10.1154) to (-19.5, -5.4654)
  arc A2 centre (-14.3, -7.7904) radius 2.325 clockwise from (-14.3, -5.4654) to (-12.8055, -6.0093)
  point P12 (-4.075, -13.3351)
  point P19 (-4.075, -13.3351)
  point P23 (-4.075, -13.3351)
  point P20 (-7.1392, -10.764)
  coincident P12 P19
  parallel L9 L14
  coincident P12 P23
  perpendicular L10 L16
  perpendicular L15 L17
  dimension "d1449" distance P19 P20 = 4
  dimension "d1450" angle L11 L14 = 50
  dimension "d1451" = 33.009
extrude "押し出し238" sketch "スケッチ99" profile of L9 L10 L14 L15 L16 L17 blind 14.14
sketch "スケッチ101" plane through (3.1962, -5.5359, 0) normal (-0.5, 0.866, 0) x axis (-0.866, -0.5, 0)
  curve K1 (-28.2882, 6.6556) -> (-28.5174, 8.3996)
  curve K2 (-28.0981, 5.1776) -> (-28.2882, 6.6556)
  line L1 (3.6906, 23.5308) -> (-28.0981, 5.1776)
  line L2 (3.6906, 26.9949) -> (3.6906, 23.5308)
  line L3 (-28.5174, 8.3996) -> (3.6906, 26.9949)
  line L4 (-8.2132, 25.3986) -> (-4.9229, 10.9499)
  line L5 (-8.9013, 10.2259) -> (-12.1916, 24.6746)
sketch "スケッチ102" plane through (-8.25, 9.239, -3.3627) normal (0.6428, -0.7198, 0.262) x axis (0.7459, 0.6661, 0)
  line L1 (10.1767, 19.5744) -> (-0.9205, 22.1707)
  line L2 (10.6323, 21.5218) -> (10.1767, 19.5744)
  line L3 (-0.4649, 24.1181) -> (10.6323, 21.5218)
  line L4 (-0.9205, 22.1707) -> (-0.4649, 24.1181)
  line L5 (6.7375, 22.433) -> (10.6323, 21.5218)
  line L6 (3.5164, 8.6648) -> (6.7375, 22.433)
  line L7 (10.6323, 21.5218) -> (7.4112, 7.7536)
loft "ロフト" sketch "スケッチ102" + "スケッチ101"
extrude "押し出し240" sketch "スケッチ75" profile of C1 C2 L7 L9 L10 L13 L14 L15 L31 L57 L64 to an object
mirror "ミラー18" mirrorStitchTolerance 0.1
mirror "ミラー20" mirrorStitchTolerance 0.1
extrude "押し出し237" cut of existing geometry blind 0.256
shell "シェル27" innerThickness 1
mirror "ミラー19" mirrorStitchTolerance 0.1
sketch "スケッチ104" plane through (0, 22.2382, -8.094) normal (0, -0.9397, 0.342) x axis (1, 0, 0)
  line L1 (-19.5, 19.378) -> (-22.5369, 19.378)
  line L2 (-19.5, 21.378) -> (-19.5, 19.378)
  line L3 (-22.5369, 21.378) -> (-19.5, 21.378)
  line L4 (-22.5369, 19.378) -> (-22.5369, 21.378)
  line L5 (-19.5, 23.378) -> (-19.5, 17.578)
  line L6 (-19.3, 23.378) -> (-19.3, 17.578)
  line L7 (-19.7, 23.378) -> (-19.7, 17.578)
  line L8 (-19.7, 17.578) -> (-19.3, 17.578)
  line L9 (-19.7, 23.378) -> (-19.3, 23.378)
  line L10 (-22.5369, 20.978) -> (-19.5, 20.978)
  line L11 (-21.3369, 19.378) -> (-21.3369, 21.378)
  line L12 (-20.9369, 19.378) -> (-20.9369, 21.378)
  perpendicular L7 L8
  perpendicular L7 L9
  dimension "d1484" = 0.2
  dimension "d1485" = -0.2 (= "-d1484")
  dimension "d1486" = -0.4
  dimension "d1487" = -1.2
  dimension "d1488" = -0.4
extrude "押し出し241" new body sketch "スケッチ104" to an object offset -0.5 from offset -0.5
mirror "ミラー22" mirrorStitchTolerance 0.1
combine "結合67"
chamfer "面取り5" distance 1
fillet "フィレット9" radius 10
shell "シェル23" innerThickness 1
combine "結合72"
extrude "押し出し228" cut of existing geometry blind 4.432
sketch "スケッチ96" plane through (0, 0, 0) normal (0, 0, 1) x axis (1, 0, 0)
  line L1 (50, -5) -> (-50, -5)
  line L2 (-50, -125) -> (-50, 125)
  line L3 (50, 125) -> (50, -125)
  line L4 (50, 1) -> (-50, 1)
  line L5 (50, 125) -> (-50, 125)
  line L6 (50, -125) -> (-50, -125)
  point P4 (-50, 125)
  point P10 (-50, 125)
  point P7 (50, 125)
  point P11 (50, 125)
  point P5 (-50, -125)
  point P12 (-50, -125)
  point P6 (50, -125)
  point P13 (50, -125)
  coincident P4 P10
  coincident P7 P11
  coincident P5 P12
  coincident P6 P13
  dimension "d1356" = -6
copy_paste_bodies "ボディのコピーと貼り付け22"
move "移動24"
extrude "押し出し229" cut sketch "スケッチ96" along normal blind 54.972
extrude "押し出し230" cut sketch "スケッチ62" profile of K1 L1 K4 L2 L4 C1 L5 L6 L7 L8 distance 41.5595
combine "結合68" bodies "box_1_0.6mm (1)"
copy_paste_bodies "ボディのコピーと貼り付け24"
move "移動26"
extrude "押し出し242" cut sketch "スケッチ61" profile of L1 L2 L3 K1 L4 L5 L6 L7 L8 K4 L9 L10 L11 K5 K8 L12 L13 L14 K9 L15 blind -127.0715 from offset 55
extrude "押し出し244" cut sketch "スケッチ96" profile of L1 L2 L3 L4 L6 along normal blind 72.612
extrude "押し出し246" cut sketch "スケッチ59" profile of L1 L3 L4 L5 L6 L9 L14 L15 C1 L16 L17 L18 L19 K5 K6 along normal blind 57.342 bodies "MB2 (1)"
extrude "押し出し243" cut sketch "スケッチ62" profile of K1 L1 K4 L2 L3 L4 C1 L5 L6 L7 L8 distance -40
